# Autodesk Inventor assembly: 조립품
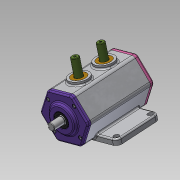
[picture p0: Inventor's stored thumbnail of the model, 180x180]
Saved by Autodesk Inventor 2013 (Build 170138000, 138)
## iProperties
Created: 2021-06
Part Number: 조립품
Document SubType Name: Assembly
Designer: hana
Author: hana
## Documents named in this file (10)
- C:\Users\hana\Desktop\710606V1021\조립품.iam
- C:\Users\hana\Desktop\710606V1021\본체.ipt
- C:\Users\hana\Desktop\710606V1021\뒷커버.ipt
- C:\Users\hana\Desktop\710606V1021\앞커버.ipt
- C:\Users\hana\Desktop\710606V1021\부시.ipt
- C:\Users\hana\Desktop\710606V1021\오일실.ipt
- C:\Users\hana\Desktop\710606V1021\베어링 6203.ipt
- C:\Users\hana\Desktop\710606V1021\편심축.ipt
- C:\Users\hana\Desktop\710606V1021\슬라이더.ipt
- C:\Users\hana\Desktop\710606V1021\볼트 M4.ipt
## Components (11 placed, 3 different names)
1. 8-오일실:1
2. 7-베어링 6203:1
3. 7-베어링 6203:2
4. 9-M4-소켓머리:1
5. 9-M4-소켓머리:2
6. 9-M4-소켓머리:3
7. 9-M4-소켓머리:4
8. 9-M4-소켓머리:5
9. 9-M4-소켓머리:6
10. 9-M4-소켓머리:7
11. 9-M4-소켓머리:8
